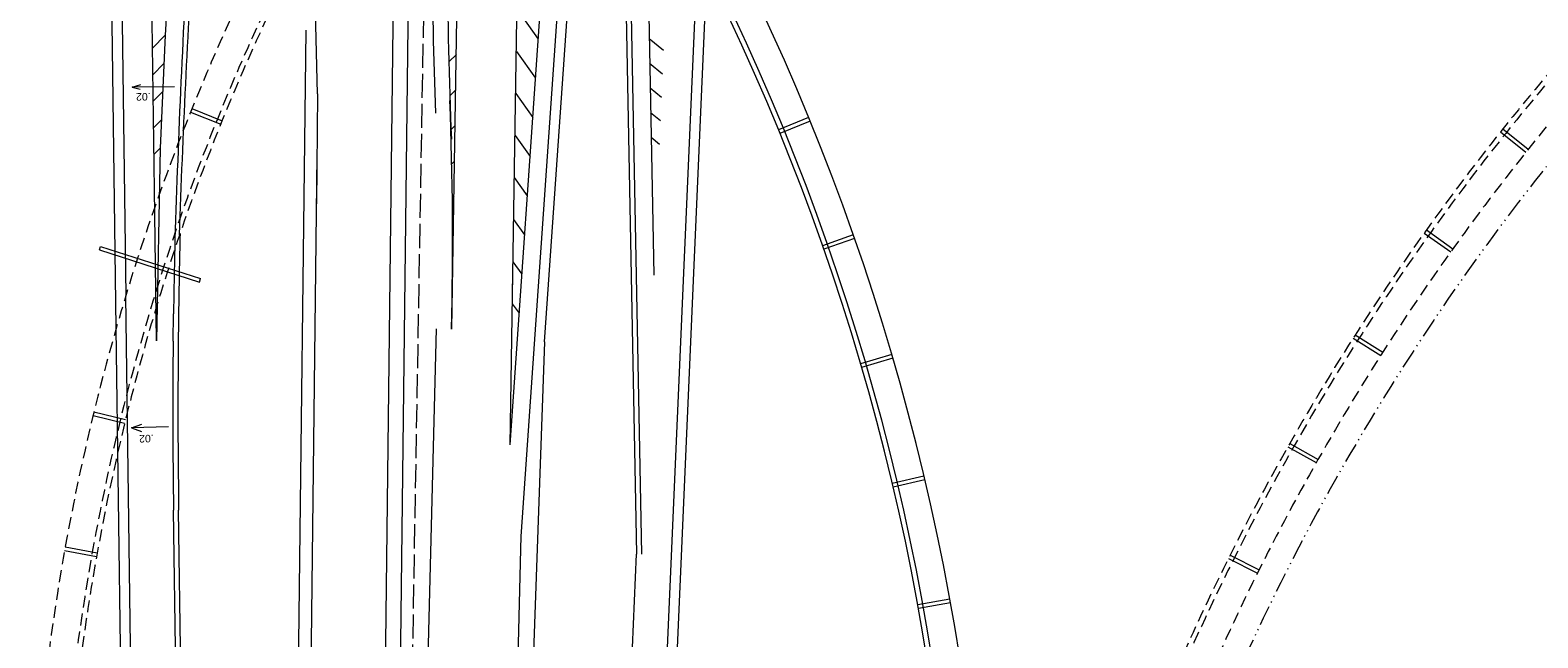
# Model space of a CAD drawing. Extents: x 2354993 to 2372084, y 6966390 to 6990057.
# Drawn here: x 2364181 to 2365387, y 6976742 to 6977227 of the extents above; entities that cross this region are included whole.
import ezdxf

# ---------------------------------------------------------------- set-up
doc = ezdxf.new("R2010")
doc.units = 0
doc.header["$LTSCALE"] = 3.2
for name, pattern in [('DASH_DOUBLE_DOT', [9.2, 5, -1.2, 0.3, -1.2, 0.3, -1.2]), ('LONG_DASHED', [7.5, 6, -1.5]), ('MEDIUM_DASHED', [4.5, 3, -1.5])]:
    doc.linetypes.add(name, pattern=pattern)
for name, color, linetype, lineweight in [('12', 7, 'Continuous', 13), ('19', 7, 'Continuous', 13), ('25', 7, 'Continuous', 13), ('4', 7, 'Continuous', 13), ('5', 7, 'Continuous', 13), ('60', 7, 'DASH_DOUBLE_DOT', 13)]:
    doc.layers.add(name, color=color, linetype=linetype, lineweight=lineweight)

msp = doc.modelspace()

# ---------------------------------------------------------------- linework, layer by layer
at = {"layer": '12'}
for p, q in [((2364309.664, 6977162.056), (2364333.781, 6977152.341)), ((2364310.787, 6977164.838), (2364334.905, 6977155.122)), ((2364803.818, 6977157.669), (2364779.77, 6977147.786)), ((2364804.955, 6977154.894), (2364780.908, 6977145.011)), ((2365356.917, 6977146.204), (2365377.315, 6977130.082)), ((2365358.787, 6977148.548), (2365379.185, 6977132.425)), ((2364839.541, 6977063.832), (2364815.008, 6977055.221)), ((2364840.532, 6977061), (2364816, 6977052.389)), ((2365295.908, 6977065.407), (2365317.122, 6977050.374)), ((2365297.654, 6977067.845), (2365318.867, 6977052.811)), ((2364236.752, 6977051.898), (2364237.672, 6977054.755)), ((2364236.752, 6977051.898), (2364316.757, 6977026.176)), ((2364237.672, 6977054.755), (2364317.676, 6977029.033)), ((2364316.757, 6977026.176), (2364317.676, 6977029.033)), ((2365239.209, 6976981.492), (2365261.181, 6976967.59)), ((2365240.825, 6976984.019), (2365262.797, 6976970.118)), ((2364870.304, 6976968.253), (2364845.355, 6976960.937)), ((2364871.145, 6976965.374), (2364846.196, 6976958.058)), ((2364231.738, 6976919.615), (2364256.99, 6976913.416)), ((2364232.453, 6976922.528), (2364257.703, 6976916.329)), ((2365186.982, 6976894.691), (2365209.651, 6976881.958)), ((2365188.462, 6976897.3), (2365211.131, 6976884.566)), ((2364896.023, 6976871.195), (2364870.725, 6976865.196)), ((2364896.712, 6976868.276), (2364871.414, 6976862.277)), ((2364234.505, 6976806.752), (2364208.917, 6976811.362)), ((2364235.035, 6976809.704), (2364209.446, 6976814.314)), ((2365139.375, 6976805.243), (2365162.678, 6976793.713)), ((2365140.716, 6976807.927), (2365164.02, 6976796.396)), ((2364916.626, 6976772.925), (2364891.049, 6976768.257)), ((2364917.162, 6976769.973), (2364891.584, 6976765.306))]:
    msp.add_line(p, q, dxfattribs=at)
at = {"layer": '19'}
for p, q in [((2364263.06, 6977181.975), (2364269.482, 6977180.223)), ((2364262.384, 6976909.676), (2364270.522, 6976906.947))]:
    msp.add_line(p, q, dxfattribs=at)
for points in [[(2364296.953, 6977182.299), (2364263.06, 6977181.975), (2364269.983, 6977184.084)], [(2364291.988, 6976910.466), (2364262.384, 6976909.676), (2364270.848, 6976912.562)]]:
    msp.add_lwpolyline(points, dxfattribs=at)
at = {"layer": '25'}
for p, q in [((2364566.988, 6977018.372), (2364567.153, 6977024.857)), ((2364295.791, 6976978.965), (2364296.078, 6977000.711))]:
    msp.add_line(p, q, dxfattribs=at)
for centre, radius, start, end in [((2372851.201, 6976799.233), 8557.951, 176.61424, 178.30543), ((2370011.158, 6976925.227), 5715.578, 178.726, 179.24328), ((2369221.259, 6976924.671), 4925.767, 179.36845, 180.93883)]:
    msp.add_arc(centre, radius, start, end, dxfattribs=at)
at = {"layer": '4'}
msp.add_line((2364592.679, 6976978.427), (2364625.192, 6977445.625), dxfattribs=at)
at = {"layer": '5'}
for p, q in [((2364250.238, 6976989.323), (2364238.582, 6977875.031)), ((2364246.695, 6977868.679), (2364257.91, 6977015.279)), ((2364280.781, 6977100.108), (2364270.924, 6977849.204)), ((2364518.585, 6976988.524), (2364528.853, 6977616.591)), ((2364565.082, 6976896.195), (2364576.847, 6977615.806)), ((2364411.249, 6977176.688), (2364406.277, 6977364.018)), ((2364655.625, 6977359.311), (2364666.287, 6976808.765)), ((2364659.624, 6977359.388), (2364670.286, 6976808.842)), ((2364673.621, 6977359.659), (2364679.974, 6977031.633)), ((2364463.051, 6976501.012), (2364473.085, 6977351.601)), ((2364468.806, 6975971.515), (2364485.084, 6977351.459)), ((2364683.134, 6976551.86), (2364717.405, 6977340.009)), ((2364690.072, 6976527.283), (2364724.81, 6977326.163)), ((2364565.082, 6976896.195), (2364591.695, 6977279.547)), ((2364574.032, 6976822.971), (2364605.662, 6977278.577)), ((2364570.688, 6977243.894), (2364587.585, 6977220.334)), ((2364401.898, 6977227.474), (2364393.18, 6976501.87)), ((2364279.294, 6977213.117), (2364289.347, 6977223.458)), ((2364676.309, 6977220.826), (2364687.791, 6977211.405)), ((2364516.32, 6977202.401), (2364522.175, 6977208.121)), ((2364570.147, 6977210.331), (2364585.412, 6977189.044)), ((2364279.574, 6977191.884), (2364288.208, 6977200.768)), ((2364676.691, 6977201.109), (2364686.976, 6977192.671)), ((2364517.2, 6977175.305), (2364521.711, 6977179.711)), ((2364677.073, 6977181.395), (2364686.162, 6977173.939)), ((2364279.853, 6977170.657), (2364287.166, 6977178.179)), ((2364411.249, 6977176.697), (2364410.263, 6977088.749)), ((2364569.605, 6977176.767), (2364583.24, 6977157.755)), ((2364280.133, 6977149.424), (2364286.216, 6977155.682)), ((2364677.455, 6977161.681), (2364685.347, 6977155.204)), ((2364518.081, 6977148.209), (2364521.246, 6977151.3)), ((2364569.064, 6977143.204), (2364581.068, 6977126.465)), ((2364280.412, 6977128.187), (2364285.358, 6977133.277)), ((2364677.836, 6977141.967), (2364684.532, 6977136.472)), ((2364410.695, 6977127.236), (2364403.178, 6976501.747)), ((2364518.533, 6977120.695), (2364520.782, 6977122.891)), ((2364568.522, 6977109.641), (2364578.896, 6977095.176)), ((2364282.372, 6976979.158), (2364280.781, 6977100.108)), ((2364518.968, 6977093.163), (2364520.317, 6977094.481)), ((2364567.981, 6977076.077), (2364576.724, 6977063.886)), ((2364567.44, 6977042.514), (2364574.551, 6977032.597)), ((2364264.089, 6976544.74), (2364257.91, 6977015.279)), ((2364566.898, 6977008.95), (2364572.379, 6977001.307)), ((2364256.409, 6976520.423), (2364250.238, 6976989.323)), ((2364493.827, 6976500.634), (2364506.22, 6976988.835)), ((2364592.679, 6976978.427), (2364576.375, 6976521.182)), ((2364300.388, 6976522.254), (2364296.153, 6976843.963)), ((2364304.541, 6976510.635), (2364300.153, 6976844.016)), ((2364565.808, 6976498.964), (2364574.043, 6976823.383)), ((2364653.122, 6976506.192), (2364666.284, 6976808.9))]:
    msp.add_line(p, q, dxfattribs=at)
at = {"layer": '5', "linetype": 'LONG_DASHED'}
msp.add_line((2364483.383, 6976501.515), (2364499.337, 6977426.187), dxfattribs=at)
at = {"layer": '5'}
msp.add_lwpolyline([(2364297.345, 6977361.394), (2364293.339, 6977292.123), (2364289.347, 6977223.458), (2364285.358, 6977133.277), (2364282.372, 6976979.158)], dxfattribs=at)
at = {"layer": '5', "linetype": 'MEDIUM_DASHED'}
for centre, radius, start, end in [((2366864.416, 6975944.503), 1927.859, 114.19653, 168.16581), ((2366864.416, 6975944.503), 1923.859, 114.19652, 168.16581), ((2366864.416, 6975944.503), 1901.859, 114.19652, 168.16581), ((2365952.337, 6976500.333), 1770.947, 142.90202, 179.54796), ((2365952.338, 6976500.332), 1748.947, 143.1115, 179.53746), ((2365952.338, 6976500.332), 1744.947, 143.1512, 179.53746)]:
    msp.add_arc(centre, radius, start, end, dxfattribs=at)
at = {"layer": '5'}
for centre, radius, start, end in [((2363030.028, 6976428.641), 1917.859, 350.16881, 38.12295), ((2363030.028, 6976428.641), 1891.859, 350.16881, 38.12295), ((2363030.028, 6976428.641), 1895.859, 350.16881, 38.12295), ((2370231.641, 6977358.541), 5729.578, 179.32409, 181.97449), ((2370231.641, 6977358.541), 5717.578, 179.32409, 182.18622), ((2373046.888, 6976763.367), 8751.449, 176.45552, 178.03092), ((2361642.852, 6977061.52), 2876.29, 358.54589, 2.18622), ((2370011.159, 6976925.25), 5711.578, 178.59763, 179.24066), ((2370025.158, 6976925.064), 5725.578, 179.24066, 180.81104)]:
    msp.add_arc(centre, radius, start, end, dxfattribs=at)
at = {"layer": '60'}
msp.add_arc((2366864.416, 6975944.503), 1881.859, 114.65077, 155.69784, dxfattribs=at)

# ---------------------------------------------------------------- texts
at = {"layer": '19', "width": 1.05}
for rotation, p in [(181.429, (2364277.701, 6977177.399)), (181.793, (2364280.158, 6976904.322))]:
    msp.add_text('.02', height=6, rotation=rotation, dxfattribs=at).set_placement(p)

doc.saveas('drawing.dxf')
